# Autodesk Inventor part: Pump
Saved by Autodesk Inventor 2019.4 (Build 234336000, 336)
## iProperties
Created: 2019-12
Part Number: Pump
Material: Generic
Document SubType Name: Modeling
Designer: Administrator
Density: 1 g/cm^3
Appearance: Default
Title: Pump v2
Author: Administrator
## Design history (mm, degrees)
feature "Body1"
body "Solid1"
